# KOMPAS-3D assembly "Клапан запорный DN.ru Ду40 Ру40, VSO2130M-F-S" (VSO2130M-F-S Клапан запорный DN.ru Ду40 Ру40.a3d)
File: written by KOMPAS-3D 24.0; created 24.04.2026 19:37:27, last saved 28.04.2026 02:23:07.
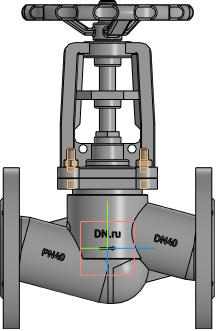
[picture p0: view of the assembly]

Document properties: Автор: DN.ru; Полное имя файла: C:\Работа\ГОТОВЫЕ ИСХОДНИКИ\VSO2130M-F-S Клапан запорный сильфонный DN.ru Ду15-100 Ру40\исходные материалы\DN40\VSO2130M-F-S Клапан запорный DN.ru Ду40 Ру40.a3d

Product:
- Component [detail]: Корпус  | qty 1  | pos. 1  | Масса: 6.9; Автор: R2D2; source file: Korpus.m3d
- Component [detail]: Деталь  | qty 1  | pos. 2  | Автор: mrdid; source file: rama.m3d
- Component [detail]: Деталь2  | qty 1  | pos. 3  | Автор: R2D2; additional columns: Типовые; source file: shturval.m3d
- Component [standard]: Шпилька М8-6gx30 ГОСТ 22032-76  | qty 4  | Масса: 0.01271; Раздел спецификации: Стандартные изделия; Рассекать на разрезах: no
- Component [standard]: Гайка М8-6H ГОСТ 5915-70  | qty 4  | Масса: 0.005548; Раздел спецификации: Стандартные изделия; Рассекать на разрезах: no
- Part/product: Клапан запорный DN.ru Ду40 Ру40  | designation VSO2130M-F-S
    Масса: 9
    Раздел спецификации: Прочие изделия
    Примечание: D090-01974

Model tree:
1. Контекстная связь:1  (with: Эскиз:2, Ребро.Элемент выдавливания:14)
2. Контекстная связь:2  (with: Контекстная связь (Деталь):2)
3. Массив по концентрической сетке:3  (4 pattern instances)
     Шаг 2 = 360
4. Эскиз:1  (with: Грань.Элемент выдавливания:9)
5. Элемент выдавливания:1  (with: Грань.Элемент выдавливания:1, Грань.Элемент выдавливания:15, Грань.Элемент выдавливания:3, Грань.Элемент выдавливания:2, Грань.Элемент выдавливания:16, Грань.Элемент выдавливания:17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)  (labels: Грань.Твердое тело1)
     Расстояние 1 = 10; Угол = 8

Referenced files in C:\Работа\ГОТОВЫЕ ИСХОДНИКИ\VSO2130M-F-S Клапан запорный сильфонный DN.ru Ду15-100 Ру40\исходные материалы\DN40\: Korpus.m3d, rama.m3d, shturval.m3d
Referenced files in C:\Program Files\ASCON\KOMPAS-3D v24\Libs\PolynomLib\DATA\vault\Methods\Kompas\3D\: PLib_Stud_1_900.m3d, PLib_Nut_OST92_900.m3d
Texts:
  Программные изделия  и базы данных
  Крепежное изделие ГОСТ
  BOSimple***PART:059b53d5-85de-be37-d9a2-ab7837626634***SHORTLOC:Root±30±20±10±120±10±20[Нет;Без покрытия;Без указания материала;-;8;30;1,25;1,25]
  BOSimple***PART:bd0d297a-feeb-be2b-2a2a-05cd1c87d412***SHORTLOC:Root±30±10±20±©{}110±10±50±60[Нет;Без покрытия;Без указания материала;-;8;1,25;13]
  VSO2130M-F-S
  Деталь2 Деталь2
  Шпилька М8-6gx30 ГОСТ 22032-76 (1)
  cut1
  Гайка М8-6H ГОСТ 5915-70 (1)
  bcut1
  hole1
  hcut1
  hole2
  Плоскость XY.Начало координат
  Plane. Начало координат
  Твердое тело1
